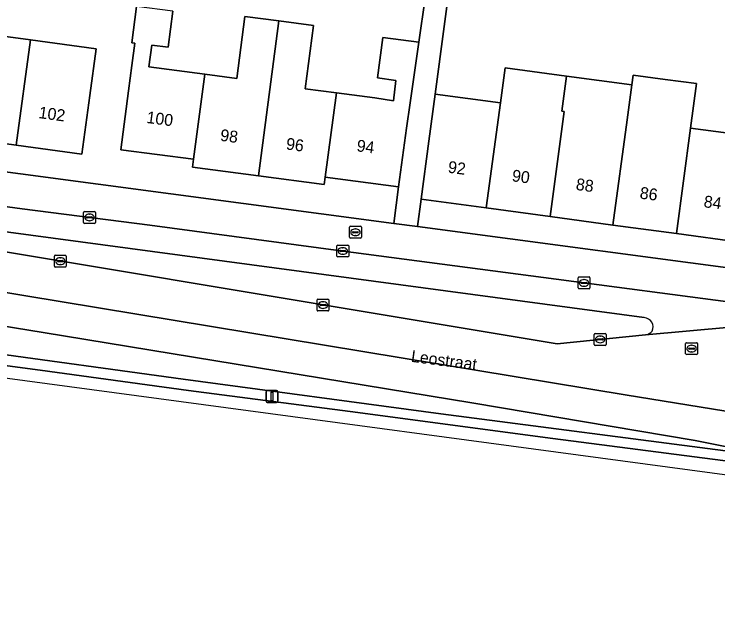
# Model space of a CAD drawing. Extents: x 161838 to 162344, y 381620 to 382160.
# Drawn here: x 161912.5 to 161971.9, y 381621.5 to 381672.5 of the extents above; entities that cross this region are included whole.
import ezdxf

# ---------------------------------------------------------------- set-up
doc = ezdxf.new("R2010")
doc.units = 0
for name, color, linetype in [('IMGEO_Berm_open', 7, 'Continuous'), ('IMGEO_Brandkraan', 7, 'Continuous'), ('IMGEO_Erf', 7, 'Continuous'), ('IMGEO_Fietspad_open', 7, 'Continuous'), ('IMGEO_Kolk', 7, 'Continuous'), ('IMGEO_Lichtmast', 7, 'Continuous'), ('IMGEO_Openbare_ruimte_label', 7, 'Continuous'), ('IMGEO_Pand', 7, 'Continuous'), ('IMGEO_Pand_nummerreeks', 7, 'Continuous'), ('IMGEO_Rijbaan_regionaal_gesloten', 7, 'Continuous'), ('IMGEO_Rioolput', 7, 'Continuous'), ('IMGEO_Verkeerseiland_open', 7, 'Continuous'), ('IMGEO_Voetpad_open', 7, 'Continuous')]:
    doc.layers.add(name, color=color, linetype=linetype)

msp = doc.modelspace()

# ---------------------------------------------------------------- linework, layer by layer
at = {"layer": 'IMGEO_Berm_open'}
for points in [[(161948.502, 381638.759), (161926.723, 381641.701), (161909.5, 381644.059), (161896.023, 381645.823), (161895.606, 381645.846), (161885.686, 381647.176), (161868.955, 381649.373)], [(161868.493, 381646.613), (161874.755, 381646.468), (161882.828, 381646.083), (161889.772, 381645.513), (161892.769, 381645.193), (161894.771, 381644.916), (161904.024, 381643.865), (161914.664, 381642.454), (161927.192, 381640.741), (161940.829, 381638.977), (161957.942, 381636.69), (161972.289, 381634.826), (161984.887, 381633.043), (161996.066, 381631.552), (162000, 381631.043), (162010.561, 381629.677), (162025.397, 381627.722), (162041.142, 381625.595)], [(162065.33, 381624.15), (162049.345, 381625.567), (162033.88, 381627.423), (162010.613, 381630.566), (162000, 381631.971), (161993.939, 381632.773), (161977.994, 381634.916), (161973.169, 381635.565), (161948.502, 381638.759)]]:
    msp.add_lwpolyline(points, dxfattribs=at)
at = {"layer": 'IMGEO_Brandkraan'}
for p, q in [((161940.78, 381653.67), (161940.78, 381654.522)), ((161940.855, 381654.596), (161941.707, 381654.596)), ((161941.268, 381654.376), (161941.293, 381654.376)), ((161941.781, 381654.522), (161941.781, 381653.67)), ((161941.707, 381653.596), (161940.855, 381653.596)), ((161941.039, 381654.09), (161941.039, 381654.102)), ((161941.477, 381654.053), (161941.079, 381654.053)), ((161941.082, 381654.139), (161941.48, 381654.139)), ((161941.291, 381653.816), (161941.266, 381653.816)), ((161941.523, 381654.102), (161941.523, 381654.09))]:
    msp.add_line(p, q, dxfattribs=at)
for points in [[(161940.78, 381653.67), (161940.78, 381654.522)], [(161940.855, 381654.596), (161941.707, 381654.596)], [(161941.781, 381654.522), (161941.781, 381653.67)], [(161941.707, 381653.596), (161940.855, 381653.596)]]:
    msp.add_lwpolyline(points, dxfattribs=at)
for centre, radius, start, end in [((161940.857, 381654.52), 0.0765, 91.55205, 178.44795), ((161940.857, 381654.52), 0.0765, 91.55205, 178.44795), ((161941.705, 381654.52), 0.0765, 1.55205, 88.44795), ((161941.705, 381654.52), 0.0765, 1.55205, 88.44795), ((161940.857, 381653.672), 0.0765, 181.55205, 268.44795), ((161940.857, 381653.672), 0.0765, 181.55205, 268.44795), ((161941.079, 381654.099), 0.0403, 85.87752, 175.75265), ((161941.076, 381654.089), 0.0366, 178.93798, 274.71019), ((161941.48, 381654.096), 0.043, 264.86636, 352.45326), ((161941.484, 381654.101), 0.0386, 1.73085, 96.63898), ((161941.705, 381653.672), 0.0765, 271.55205, 358.44795), ((161941.705, 381653.672), 0.0765, 271.55205, 358.44795)]:
    msp.add_arc(centre, radius, start, end, dxfattribs=at)
for centre, major_axis, ratio, start_param, end_param in [((161941.267, 381654.096), (-0.387, 0.002), 0.722429, 4.712389, 7.853982), ((161941.292, 381654.096), (-0.39, 0.002), 0.717154, 1.570796, 4.712389)]:
    msp.add_ellipse(centre, major_axis=major_axis, ratio=ratio, start_param=start_param, end_param=end_param, dxfattribs=at)
at = {"layer": 'IMGEO_Erf'}
for points in [[(161925.854, 381672.751), (161925.454, 381669.719), (161924.085, 381669.9), (161923.841, 381668.05), (161928.56, 381667.429), (161931.257, 381667.074), (161931.947, 381672.316), (161934.812, 381671.939), (161937.744, 381671.553), (161937.04, 381666.206), (161939.668, 381665.86), (161942.915, 381665.432), (161944.495, 381665.194), (161944.695, 381666.91), (161943.138, 381667.129), (161943.588, 381670.543), (161946.636, 381670.142), (161947.691, 381677.6)], [(161949.581, 381677.64), (161948.005, 381665.745), (161953.526, 381665.011), (161953.926, 381667.98), (161959.095, 381667.283), (161964.621, 381666.538), (161964.732, 381667.363), (161967.427, 381667), (161970.089, 381666.641), (161969.581, 381662.875), (161974.91, 381662.166)], [(161906.825, 381659.836), (161944.516, 381654.835), (161944.926, 381657.922), (161938.73, 381658.738), (161938.648, 381658.117), (161933.088, 381658.849), (161927.526, 381659.582), (161927.614, 381660.256), (161921.474, 381661.065), (161922.127, 381666.023), (161922.41, 381668.169), (161922.667, 381670.055), (161922.395, 381670.091), (161922.799, 381673.154)], [(161908.368, 381671.071), (161913.854, 381670.333), (161919.4, 381669.587), (161918.861, 381665.644), (161918.184, 381660.69), (161912.64, 381661.448), (161907.147, 381662.199)]]:
    msp.add_lwpolyline(points, dxfattribs=at)
msp.add_lwpolyline([(161968.382, 381653.983), (161963.025, 381654.706), (161957.707, 381655.423), (161952.331, 381656.148), (161946.833, 381656.89), (161946.525, 381654.568), (161977.386, 381650.474), (161978.924, 381650.27), (161979.223, 381652.521), (161973.709, 381653.265)], close=True, dxfattribs=at)
at = {"layer": 'IMGEO_Fietspad_open'}
for points in [[(161965.767, 381645.44), (161976.702, 381646.425), (161976.924, 381647.666), (161974.233, 381648.03), (161957.169, 381650.266), (161940.036, 381652.534), (161923.921, 381654.69), (161913.151, 381656.071), (161900.703, 381657.764), (161892.731, 381658.781)], [(161890.986, 381656.917), (161965.669, 381646.893)]]:
    msp.add_lwpolyline(points, dxfattribs=at)
for centre, radius, start, end in [((161965.574, 381646.021), 0.877, 32.48251, 83.77861), ((161965.564, 381646.111), 0.842, 335.11514, 26.91144), ((161965.646, 381646.306), 0.875, 277.92675, 321.09917)]:
    msp.add_arc(centre, radius, start, end, dxfattribs=at)
at = {"layer": 'IMGEO_Kolk'}
for p, q in [((161918.323, 381654.919), (161918.323, 381655.771)), ((161918.398, 381655.845), (161919.25, 381655.845)), ((161918.582, 381655.339), (161918.582, 381655.351)), ((161918.625, 381655.388), (161919.023, 381655.388)), ((161918.811, 381655.625), (161918.836, 381655.625)), ((161919.066, 381655.351), (161919.066, 381655.339)), ((161919.324, 381655.771), (161919.324, 381654.919)), ((161919.25, 381654.845), (161918.398, 381654.845)), ((161919.02, 381655.302), (161918.622, 381655.302)), ((161918.834, 381655.065), (161918.809, 381655.065)), ((161939.783, 381653.013), (161940.635, 381653.013)), ((161939.708, 381652.087), (161939.708, 381652.939)), ((161939.967, 381652.507), (161939.967, 381652.519)), ((161940.405, 381652.47), (161940.007, 381652.47)), ((161940.01, 381652.556), (161940.408, 381652.556)), ((161940.196, 381652.793), (161940.221, 381652.793)), ((161940.451, 381652.519), (161940.451, 381652.507)), ((161940.709, 381652.939), (161940.709, 381652.087)), ((161915.86, 381651.229), (161915.86, 381652.081)), ((161915.935, 381652.155), (161916.787, 381652.155)), ((161916.348, 381651.935), (161916.373, 381651.935)), ((161916.861, 381652.081), (161916.861, 381651.229)), ((161940.635, 381652.013), (161939.783, 381652.013)), ((161940.219, 381652.233), (161940.194, 381652.233)), ((161916.119, 381651.649), (161916.119, 381651.661)), ((161916.557, 381651.612), (161916.159, 381651.612)), ((161916.162, 381651.698), (161916.56, 381651.698)), ((161916.371, 381651.375), (161916.346, 381651.375)), ((161916.603, 381651.661), (161916.603, 381651.649)), ((161916.787, 381651.155), (161915.935, 381651.155)), ((161960.079, 381649.394), (161960.079, 381650.246)), ((161960.154, 381650.32), (161961.006, 381650.32)), ((161960.567, 381650.1), (161960.592, 381650.1)), ((161961.08, 381650.246), (161961.08, 381649.394)), ((161960.338, 381649.814), (161960.338, 381649.826)), ((161960.776, 381649.777), (161960.378, 381649.777)), ((161960.381, 381649.863), (161960.779, 381649.863)), ((161960.59, 381649.54), (161960.565, 381649.54)), ((161960.822, 381649.826), (161960.822, 381649.814)), ((161961.006, 381649.32), (161960.154, 381649.32)), ((161938.034, 381647.526), (161938.034, 381648.378)), ((161938.109, 381648.452), (161938.961, 381648.452)), ((161938.522, 381648.232), (161938.547, 381648.232)), ((161939.035, 381648.378), (161939.035, 381647.526)), ((161938.293, 381647.946), (161938.293, 381647.958)), ((161938.731, 381647.909), (161938.333, 381647.909)), ((161938.336, 381647.995), (161938.734, 381647.995)), ((161938.545, 381647.672), (161938.52, 381647.672)), ((161938.777, 381647.958), (161938.777, 381647.946)), ((161938.961, 381647.452), (161938.109, 381647.452)), ((161961.444, 381644.621), (161961.444, 381645.473)), ((161961.519, 381645.547), (161962.371, 381645.547)), ((161961.932, 381645.327), (161961.957, 381645.327)), ((161962.445, 381645.473), (161962.445, 381644.621)), ((161961.703, 381645.041), (161961.703, 381645.053)), ((161962.141, 381645.004), (161961.743, 381645.004)), ((161961.746, 381645.09), (161962.144, 381645.09)), ((161961.955, 381644.767), (161961.93, 381644.767)), ((161962.187, 381645.053), (161962.187, 381645.041)), ((161962.371, 381644.547), (161961.519, 381644.547))]:
    msp.add_line(p, q, dxfattribs=at)
for points in [[(161918.323, 381654.919), (161918.323, 381655.771)], [(161918.398, 381655.845), (161919.25, 381655.845)], [(161919.324, 381655.771), (161919.324, 381654.919)], [(161919.25, 381654.845), (161918.398, 381654.845)], [(161939.783, 381653.013), (161940.635, 381653.013)], [(161939.708, 381652.087), (161939.708, 381652.939)], [(161940.709, 381652.939), (161940.709, 381652.087)], [(161915.86, 381651.229), (161915.86, 381652.081)], [(161915.935, 381652.155), (161916.787, 381652.155)], [(161916.861, 381652.081), (161916.861, 381651.229)], [(161940.635, 381652.013), (161939.783, 381652.013)], [(161916.787, 381651.155), (161915.935, 381651.155)], [(161960.079, 381649.394), (161960.079, 381650.246)], [(161960.154, 381650.32), (161961.006, 381650.32)], [(161961.08, 381650.246), (161961.08, 381649.394)], [(161961.006, 381649.32), (161960.154, 381649.32)], [(161938.034, 381647.526), (161938.034, 381648.378)], [(161938.109, 381648.452), (161938.961, 381648.452)], [(161939.035, 381648.378), (161939.035, 381647.526)], [(161938.961, 381647.452), (161938.109, 381647.452)], [(161961.444, 381644.621), (161961.444, 381645.473)], [(161961.519, 381645.547), (161962.371, 381645.547)], [(161962.445, 381645.473), (161962.445, 381644.621)], [(161962.371, 381644.547), (161961.519, 381644.547)]]:
    msp.add_lwpolyline(points, dxfattribs=at)
for centre, radius, start, end in [((161918.4, 381655.769), 0.0765, 91.55205, 178.44795), ((161918.4, 381655.769), 0.0765, 91.55205, 178.44795), ((161918.622, 381655.348), 0.0403, 85.87752, 175.75265), ((161919.027, 381655.35), 0.0386, 1.73085, 96.63898), ((161919.248, 381655.769), 0.0765, 1.55205, 88.44795), ((161919.248, 381655.769), 0.0765, 1.55205, 88.44795), ((161918.4, 381654.921), 0.0765, 181.55205, 268.44795), ((161918.4, 381654.921), 0.0765, 181.55205, 268.44795), ((161918.619, 381655.338), 0.0366, 178.93798, 274.71019), ((161919.023, 381655.345), 0.043, 264.86636, 352.45326), ((161919.248, 381654.921), 0.0765, 271.55205, 358.44795), ((161919.248, 381654.921), 0.0765, 271.55205, 358.44795), ((161939.785, 381652.937), 0.0765, 91.55205, 178.44795), ((161939.785, 381652.937), 0.0765, 91.55205, 178.44795), ((161940.633, 381652.937), 0.0765, 1.55205, 88.44795), ((161940.633, 381652.937), 0.0765, 1.55205, 88.44795), ((161940.007, 381652.516), 0.0403, 85.87752, 175.75265), ((161940.004, 381652.506), 0.0366, 178.93798, 274.71019), ((161940.408, 381652.513), 0.043, 264.86636, 352.45326), ((161940.412, 381652.518), 0.0386, 1.73085, 96.63898), ((161915.937, 381652.079), 0.0765, 91.55205, 178.44795), ((161915.937, 381652.079), 0.0765, 91.55205, 178.44795), ((161916.785, 381652.079), 0.0765, 1.55205, 88.44795), ((161916.785, 381652.079), 0.0765, 1.55205, 88.44795), ((161939.785, 381652.089), 0.0765, 181.55205, 268.44795), ((161939.785, 381652.089), 0.0765, 181.55205, 268.44795), ((161940.633, 381652.089), 0.0765, 271.55205, 358.44795), ((161940.633, 381652.089), 0.0765, 271.55205, 358.44795), ((161915.937, 381651.231), 0.0765, 181.55205, 268.44795), ((161915.937, 381651.231), 0.0765, 181.55205, 268.44795), ((161916.159, 381651.658), 0.0403, 85.87752, 175.75265), ((161916.156, 381651.648), 0.0366, 178.93798, 274.71019), ((161916.56, 381651.655), 0.043, 264.86636, 352.45326), ((161916.564, 381651.66), 0.0386, 1.73085, 96.63898), ((161916.785, 381651.231), 0.0765, 271.55205, 358.44795), ((161916.785, 381651.231), 0.0765, 271.55205, 358.44795), ((161960.156, 381650.244), 0.0765, 91.55205, 178.44795), ((161960.156, 381650.244), 0.0765, 91.55205, 178.44795), ((161961.004, 381650.244), 0.0765, 1.55205, 88.44795), ((161961.004, 381650.244), 0.0765, 1.55205, 88.44795), ((161960.378, 381649.823), 0.0403, 85.87752, 175.75265), ((161960.375, 381649.813), 0.0366, 178.93798, 274.71019), ((161960.779, 381649.82), 0.043, 264.86636, 352.45326), ((161960.783, 381649.825), 0.0386, 1.73085, 96.63898), ((161960.156, 381649.396), 0.0765, 181.55205, 268.44795), ((161960.156, 381649.396), 0.0765, 181.55205, 268.44795), ((161961.004, 381649.396), 0.0765, 271.55205, 358.44795), ((161961.004, 381649.396), 0.0765, 271.55205, 358.44795), ((161938.111, 381648.376), 0.0765, 91.55205, 178.44795), ((161938.111, 381648.376), 0.0765, 91.55205, 178.44795), ((161938.959, 381648.376), 0.0765, 1.55205, 88.44795), ((161938.959, 381648.376), 0.0765, 1.55205, 88.44795), ((161938.333, 381647.955), 0.0403, 85.87752, 175.75265), ((161938.33, 381647.945), 0.0366, 178.93798, 274.71019), ((161938.734, 381647.952), 0.043, 264.86636, 352.45326), ((161938.738, 381647.957), 0.0386, 1.73085, 96.63898), ((161938.111, 381647.528), 0.0765, 181.55205, 268.44795), ((161938.111, 381647.528), 0.0765, 181.55205, 268.44795), ((161938.959, 381647.528), 0.0765, 271.55205, 358.44795), ((161938.959, 381647.528), 0.0765, 271.55205, 358.44795), ((161961.521, 381645.471), 0.0765, 91.55205, 178.44795), ((161961.521, 381645.471), 0.0765, 91.55205, 178.44795), ((161962.369, 381645.471), 0.0765, 1.55205, 88.44795), ((161962.369, 381645.471), 0.0765, 1.55205, 88.44795), ((161961.743, 381645.05), 0.0403, 85.87752, 175.75265), ((161961.74, 381645.04), 0.0366, 178.93798, 274.71019), ((161962.144, 381645.047), 0.043, 264.86636, 352.45326), ((161962.148, 381645.052), 0.0386, 1.73085, 96.63898), ((161961.521, 381644.623), 0.0765, 181.55205, 268.44795), ((161961.521, 381644.623), 0.0765, 181.55205, 268.44795), ((161962.369, 381644.623), 0.0765, 271.55205, 358.44795), ((161962.369, 381644.623), 0.0765, 271.55205, 358.44795)]:
    msp.add_arc(centre, radius, start, end, dxfattribs=at)
for centre, major_axis, ratio, start_param, end_param in [((161918.81, 381655.345), (-0.387, 0.002), 0.722429, 4.712389, 7.853982), ((161918.835, 381655.345), (-0.39, 0.002), 0.717154, 1.570796, 4.712389), ((161940.195, 381652.513), (-0.387, 0.002), 0.722429, 4.712389, 7.853982), ((161940.22, 381652.513), (-0.39, 0.002), 0.717154, 1.570796, 4.712389), ((161916.347, 381651.655), (-0.387, 0.002), 0.722429, 4.712389, 7.853982), ((161916.372, 381651.655), (-0.39, 0.002), 0.717154, 1.570796, 4.712389), ((161960.566, 381649.82), (-0.387, 0.002), 0.722429, 4.712389, 7.853982), ((161960.591, 381649.82), (-0.39, 0.002), 0.717154, 1.570796, 4.712389), ((161938.521, 381647.952), (-0.387, 0.002), 0.722429, 4.712389, 7.853982), ((161938.546, 381647.952), (-0.39, 0.002), 0.717154, 1.570796, 4.712389), ((161961.931, 381645.047), (-0.387, 0.002), 0.722429, 4.712389, 7.853982), ((161961.956, 381645.047), (-0.39, 0.002), 0.717154, 1.570796, 4.712389)]:
    msp.add_ellipse(centre, major_axis=major_axis, ratio=ratio, start_param=start_param, end_param=end_param, dxfattribs=at)
at = {"layer": 'IMGEO_Lichtmast'}
for p, q in [((161933.733, 381639.832), (161933.733, 381640.632)), ((161933.733, 381640.632), (161933.733, 381639.832)), ((161933.833, 381640.732), (161934.623, 381640.732)), ((161934.623, 381640.732), (161933.833, 381640.732)), ((161934.723, 381640.632), (161934.723, 381639.832)), ((161934.723, 381639.832), (161934.723, 381640.632)), ((161934.623, 381639.732), (161933.833, 381639.732)), ((161933.833, 381639.732), (161934.623, 381639.732))]:
    msp.add_line(p, q, dxfattribs=at)
msp.add_lwpolyline([(161934.153, 381640.607), (161934.303, 381640.607), (161934.303, 381639.857), (161934.153, 381639.857), (161934.153, 381640.607)], dxfattribs=at)
for centre, start, end in [((161933.833, 381640.632), 90, 180), ((161933.833, 381640.632), 90, 180), ((161934.623, 381640.632), 0, 90), ((161934.623, 381640.632), 360, 90), ((161933.833, 381639.832), 180, 270), ((161933.833, 381639.832), 180, 270), ((161934.623, 381639.832), 270, 0), ((161934.623, 381639.832), 270, 0)]:
    msp.add_arc(centre, 0.1, start, end, dxfattribs=at)
at = {"layer": 'IMGEO_Pand'}
for points in [[(161928.56, 381667.429), (161923.841, 381668.05), (161924.085, 381669.9), (161925.454, 381669.719), (161925.854, 381672.751), (161922.799, 381673.154), (161922.395, 381670.091), (161922.667, 381670.055), (161922.41, 381668.169), (161922.127, 381666.023), (161921.474, 381661.065), (161927.614, 381660.256)], [(161928.56, 381667.429), (161927.614, 381660.256), (161927.526, 381659.582), (161933.088, 381658.849), (161934.812, 381671.939), (161931.947, 381672.316), (161931.257, 381667.074)], [(161934.812, 381671.939), (161933.088, 381658.849), (161938.648, 381658.117), (161938.73, 381658.738), (161939.668, 381665.86), (161937.04, 381666.206), (161937.744, 381671.553)], [(161913.854, 381670.333), (161908.368, 381671.071), (161907.147, 381662.199), (161912.64, 381661.448)], [(161913.854, 381670.333), (161912.64, 381661.448), (161918.184, 381660.69), (161918.861, 381665.644), (161919.4, 381669.587)], [(161945.913, 381665.031), (161946.636, 381670.142), (161943.588, 381670.543), (161943.138, 381667.129), (161944.695, 381666.91), (161944.495, 381665.194), (161942.915, 381665.432), (161939.668, 381665.86), (161938.73, 381658.738), (161944.926, 381657.922), (161945.579, 381662.88)], [(161958.904, 381664.295), (161958.696, 381664.323), (161959.095, 381667.283), (161953.926, 381667.98), (161953.526, 381665.011), (161952.331, 381656.148), (161957.707, 381655.423)], [(161964.223, 381663.588), (161964.621, 381666.538), (161959.095, 381667.283), (161958.696, 381664.323), (161958.904, 381664.295), (161957.707, 381655.423), (161963.025, 381654.706)], [(161969.581, 381662.875), (161970.089, 381666.641), (161967.427, 381667), (161964.732, 381667.363), (161964.621, 381666.538), (161964.223, 381663.588), (161963.025, 381654.706), (161968.382, 381653.983)], [(161952.331, 381656.148), (161953.526, 381665.011), (161948.005, 381665.745), (161947.479, 381661.775), (161946.833, 381656.89)], [(161974.91, 381662.166), (161969.581, 381662.875), (161968.382, 381653.983), (161973.709, 381653.265)]]:
    msp.add_lwpolyline(points, close=True, dxfattribs=at)
at = {"layer": 'IMGEO_Rijbaan_regionaal_gesloten'}
for points in [[(161878.941, 381658.286), (161870.319, 381660.342), (161869.776, 381655.978), (161887.687, 381652.965), (161964.232, 381640.351), (161981.6, 381637.531), (162040.889, 381629.888), (162052.073, 381628.524), (162065.762, 381627.224), (162066.237, 381630.607)], [(161980.412, 381641.904), (161976.702, 381646.425), (161965.767, 381645.44), (161958.321, 381644.667), (161892.953, 381655.58)], [(162041.142, 381625.595), (162025.397, 381627.722), (162010.561, 381629.677), (162000, 381631.043), (161996.066, 381631.552), (161984.887, 381633.043), (161972.289, 381634.826), (161957.942, 381636.69), (161940.829, 381638.977), (161927.192, 381640.741), (161914.664, 381642.454), (161904.024, 381643.865), (161894.771, 381644.916), (161892.769, 381645.193), (161889.772, 381645.513), (161882.828, 381646.083), (161874.755, 381646.468), (161868.493, 381646.613), (161868.307, 381645.629), (161885.462, 381645.334), (162004.925, 381629.287), (162063.24, 381621.454)]]:
    msp.add_lwpolyline(points, dxfattribs=at)
for points in [[(161869.776, 381655.978), (161869.396, 381652.918), (161883.44, 381650.767), (161914.926, 381645.64), (161951.098, 381639.708), (161969.971, 381636.522), (161977.994, 381634.916), (161993.939, 381632.773), (162000, 381631.971), (162010.613, 381630.566), (162033.88, 381627.423), (162049.345, 381625.567), (162065.33, 381624.15), (162065.762, 381627.224), (162052.073, 381628.524), (162040.889, 381629.888), (161981.6, 381637.531), (161964.232, 381640.351), (161887.687, 381652.965)], [(161869.396, 381652.918), (161868.955, 381649.373), (161885.686, 381647.176), (161895.606, 381645.846), (161896.023, 381645.823), (161909.5, 381644.059), (161926.723, 381641.701), (161948.502, 381638.759), (161973.169, 381635.565), (161977.994, 381634.916), (161969.971, 381636.522), (161951.098, 381639.708), (161914.926, 381645.64), (161883.44, 381650.767)]]:
    msp.add_lwpolyline(points, close=True, dxfattribs=at)
at = {"layer": 'IMGEO_Rioolput'}
for p, q in [((161969.161, 381643.846), (161969.161, 381644.698)), ((161969.236, 381644.772), (161970.088, 381644.772)), ((161970.162, 381644.698), (161970.162, 381643.846)), ((161969.42, 381644.266), (161969.42, 381644.278)), ((161969.858, 381644.229), (161969.46, 381644.229)), ((161969.463, 381644.315), (161969.861, 381644.315)), ((161969.649, 381644.552), (161969.674, 381644.552)), ((161969.904, 381644.278), (161969.904, 381644.266)), ((161970.088, 381643.772), (161969.236, 381643.772)), ((161969.672, 381643.992), (161969.647, 381643.992))]:
    msp.add_line(p, q, dxfattribs=at)
for points in [[(161969.161, 381643.846), (161969.161, 381644.698)], [(161969.236, 381644.772), (161970.088, 381644.772)], [(161970.162, 381644.698), (161970.162, 381643.846)], [(161970.088, 381643.772), (161969.236, 381643.772)]]:
    msp.add_lwpolyline(points, dxfattribs=at)
for centre, radius, start, end in [((161969.238, 381644.696), 0.0765, 91.55205, 178.44795), ((161969.238, 381644.696), 0.0765, 91.55205, 178.44795), ((161970.086, 381644.696), 0.0765, 1.55205, 88.44795), ((161970.086, 381644.696), 0.0765, 1.55205, 88.44795), ((161969.46, 381644.275), 0.0403, 85.87752, 175.75265), ((161969.457, 381644.265), 0.0366, 178.93798, 274.71019), ((161969.861, 381644.272), 0.043, 264.86636, 352.45326), ((161969.865, 381644.277), 0.0386, 1.73085, 96.63898), ((161969.238, 381643.848), 0.0765, 181.55205, 268.44795), ((161969.238, 381643.848), 0.0765, 181.55205, 268.44795), ((161970.086, 381643.848), 0.0765, 271.55205, 358.44795), ((161970.086, 381643.848), 0.0765, 271.55205, 358.44795)]:
    msp.add_arc(centre, radius, start, end, dxfattribs=at)
for centre, major_axis, ratio, start_param, end_param in [((161969.648, 381644.272), (-0.387, 0.002), 0.722429, 4.712389, 7.853982), ((161969.673, 381644.272), (-0.39, 0.002), 0.717154, 1.570796, 4.712389)]:
    msp.add_ellipse(centre, major_axis=major_axis, ratio=ratio, start_param=start_param, end_param=end_param, dxfattribs=at)
at = {"layer": 'IMGEO_Verkeerseiland_open'}
for points in [[(161965.669, 381646.893), (161890.986, 381656.917)], [(161892.953, 381655.58), (161958.321, 381644.667), (161965.767, 381645.44)]]:
    msp.add_lwpolyline(points, dxfattribs=at)
for centre, radius, start, end in [((161965.574, 381646.021), 0.877, 32.48251, 83.77861), ((161965.564, 381646.111), 0.842, 335.11514, 26.91144), ((161965.646, 381646.306), 0.875, 277.92675, 321.09917)]:
    msp.add_arc(centre, radius, start, end, dxfattribs=at)
at = {"layer": 'IMGEO_Voetpad_open'}
for points in [[(161909.889, 381682.955), (161913.27, 381682.538), (161917.232, 381681.97), (161921.491, 381681.359), (161947.691, 381677.6), (161946.636, 381670.142), (161945.913, 381665.031), (161945.579, 381662.88), (161944.926, 381657.922), (161944.516, 381654.835), (161946.525, 381654.568), (161946.833, 381656.89), (161947.479, 381661.775), (161948.005, 381665.745), (161949.581, 381677.64), (161950.995, 381677.449), (161955.128, 381676.892), (161959.253, 381676.337), (161960.325, 381676.197), (161961.689, 381676.019), (161965.824, 381675.461), (161969.95, 381674.905), (161972.382, 381674.573)], [(161980.874, 381650.011), (161978.924, 381650.27), (161977.386, 381650.474), (161946.525, 381654.568), (161944.516, 381654.835), (161906.825, 381659.836), (161902.061, 381660.536), (161897.485, 381661.208), (161892.748, 381661.903), (161887.786, 381662.632), (161881.751, 381664.382), (161876.207, 381665.989), (161865.106, 381669.207), (161866.008, 381675.715), (161866.135, 381676.635), (161860.622, 381677.32), (161858.868, 381677.544)], [(161892.731, 381658.781), (161900.703, 381657.764), (161913.151, 381656.071), (161923.921, 381654.69), (161940.036, 381652.534), (161957.169, 381650.266), (161974.233, 381648.03), (161976.924, 381647.666), (161989.428, 381645.974), (162000, 381644.547), (162003.764, 381644.039), (162016.672, 381642.306), (162030.858, 381640.392), (162035.682, 381639.818), (162041.638, 381639.11), (162044.769, 381638.755), (162057.572, 381637.304)]]:
    msp.add_lwpolyline(points, dxfattribs=at)

# ---------------------------------------------------------------- texts
at = {"layer": 'IMGEO_Openbare_ruimte_label'}
msp.add_text('Leostraat', height=1, rotation=352.41293, dxfattribs=at).set_placement((161945.935, 381643.165))
at = {"layer": 'IMGEO_Pand_nummerreeks'}
for s, rotation, p in [('102', 352.2135, (161914.489, 381663.739)), ('100', 352.494, (161923.601, 381663.327)), ('98', 352.49615, (161929.819, 381661.822)), ('96', 352.49615, (161935.377, 381661.089)), ('94', 352.49998, (161941.338, 381660.936)), ('92', 352.31789, (161949.047, 381659.135)), ('90', 352.31664, (161954.451, 381658.406)), ('88', 352.31664, (161959.849, 381657.678)), ('86', 352.31664, (161965.245, 381656.949)), ('84', 352.31789, (161970.643, 381656.221))]:
    msp.add_text(s, height=1, rotation=rotation, dxfattribs=at).set_placement(p)

doc.saveas('drawing.dxf')
